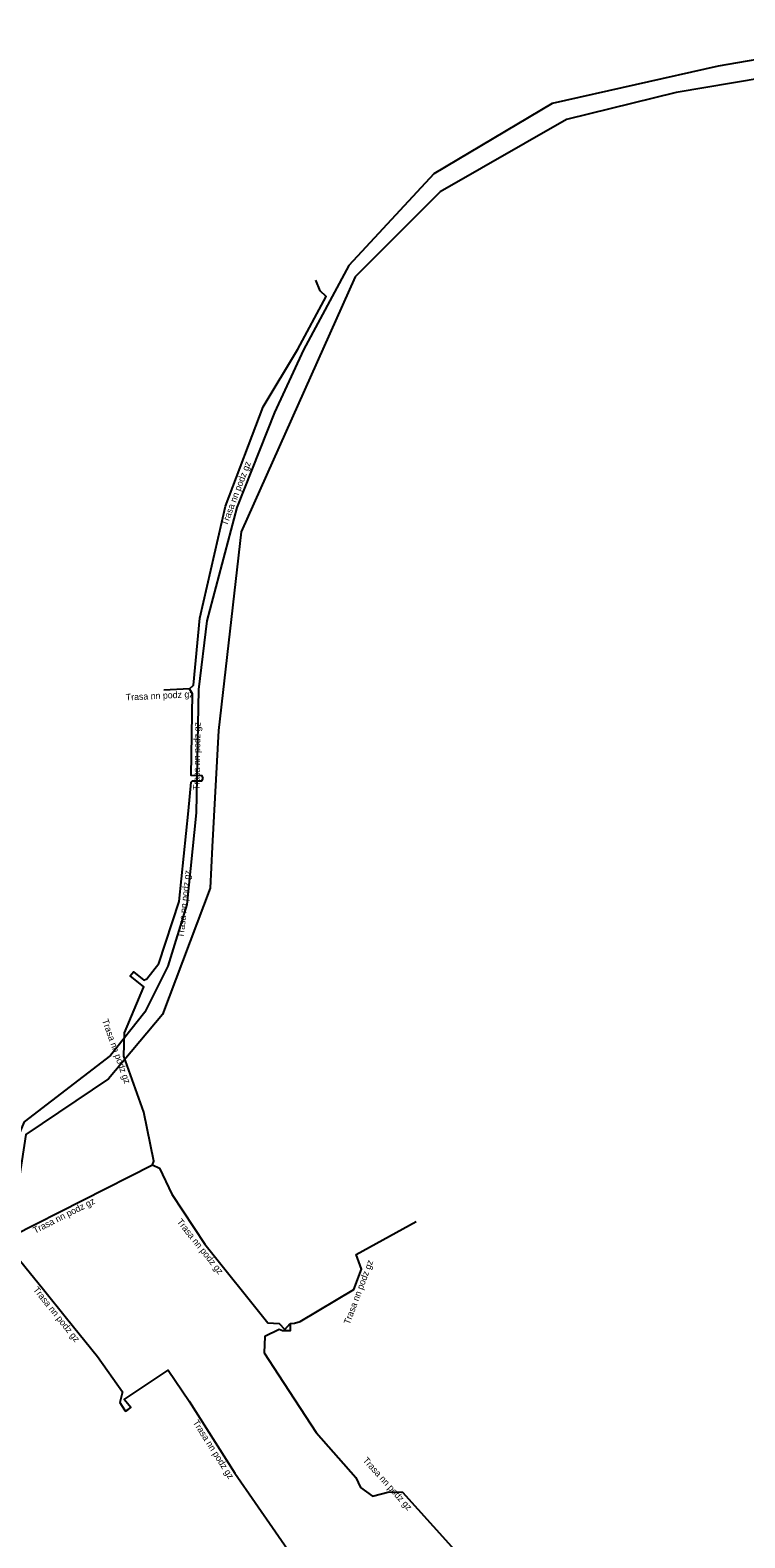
# Model space of a CAD drawing. Extents: x -484846 to -484244, y -1128177 to -1127608.
# Drawn here: x -484548.8 to -484494.4, y -1127972.3 to -1127857.6 of the extents above; entities that cross this region are included whole.
import ezdxf

# ---------------------------------------------------------------- set-up
doc = ezdxf.new("R2010")
doc.units = 0
for name, color, linetype in [('Popiskový text - Ostatní atributy Trasy', 7, 'Continuous'), ('Spojnice NN', 7, 'Continuous'), ('Spojnice VN', 7, 'Continuous')]:
    doc.layers.add(name, color=color, linetype=linetype)

msp = doc.modelspace()

# ---------------------------------------------------------------- linework, layer by layer
at = {"layer": 'Spojnice NN'}
for points in [[(-484536.68, -1127907.69), (-484536.38, -1127907.4), (-484535.89, -1127902.32), (-484533.94, -1127893.79), (-484531.09, -1127886.25), (-484528.45, -1127881.86), (-484526.3, -1127877.86), (-484526.76, -1127877.43), (-484527.07, -1127876.6)], [(-484536.68, -1127907.69), (-484538.64, -1127907.79)], [(-484535.65, -1127914.51), (-484535.73, -1127914.3), (-484536.56, -1127914.28), (-484536.47, -1127908.06), (-484536.61, -1127907.82), (-484536.68, -1127907.69)], [(-484541.07, -1127929.38), (-484540.94, -1127929.22), (-484540.17, -1127929.84), (-484539.92, -1127929.74), (-484539.03, -1127928.57), (-484537.48, -1127923.87), (-484536.76, -1127916.96), (-484536.56, -1127914.8), (-484536.47, -1127914.69), (-484535.74, -1127914.7), (-484535.65, -1127914.51)], [(-484539.5, -1127943.9), (-484539.39, -1127943.62), (-484540.17, -1127939.88), (-484541.69, -1127935.63), (-484541.63, -1127933.85), (-484540.15, -1127930.36), (-484541.19, -1127929.53), (-484541.07, -1127929.38)], [(-484550.99, -1127949.7), (-484550.64, -1127949.47), (-484550.11, -1127949.26), (-484539.5, -1127943.9)], [(-484539.5, -1127943.9), (-484538.97, -1127944.16), (-484538.02, -1127946.13), (-484535.51, -1127949.92), (-484530.72, -1127955.92), (-484529.87, -1127955.96), (-484529.44, -1127956.42), (-484529.04, -1127955.97)], [(-484529.04, -1127955.97), (-484528.71, -1127955.95), (-484528.26, -1127955.81), (-484524.19, -1127953.38), (-484523.61, -1127951.83), (-484524, -1127950.71), (-484519.44, -1127948.2)], [(-484550.99, -1127949.7), (-484550.63, -1127949.87), (-484547.79, -1127953.38), (-484546.05, -1127955.55), (-484543.69, -1127958.48), (-484541.77, -1127961.17), (-484541.98, -1127961.96), (-484541.62, -1127962.54), (-484541.55, -1127962.64), (-484541.35, -1127962.5)], [(-484529.04, -1127955.97), (-484529.03, -1127956.51), (-484529.62, -1127956.51), (-484529.86, -1127956.41), (-484530.96, -1127956.96), (-484531.02, -1127958.2), (-484529.91, -1127959.88), (-484527.05, -1127964.26), (-484524.04, -1127967.67), (-484523.69, -1127968.43), (-484522.78, -1127969.09), (-484521.5, -1127968.78), (-484520.49, -1127968.8), (-484514.43, -1127975.5), (-484511.22, -1127979.06), (-484508.05, -1127982.62), (-484507.53, -1127982.75), (-484506.74, -1127982.23)], [(-484541.35, -1127962.5), (-484541.16, -1127962.36), (-484541.65, -1127961.74), (-484538.3, -1127959.51), (-484536.72, -1127961.87), (-484533.23, -1127967.36), (-484528.6, -1127974.03), (-484531.16, -1127976.24), (-484530.58, -1127976.61)]]:
    msp.add_lwpolyline(points, dxfattribs=at)
at = {"layer": 'Spojnice VN'}
for points in [[(-484480.59, -1127857.59), (-484496.47, -1127860.34), (-484509.11, -1127863.16), (-484518.1, -1127868.51), (-484524.57, -1127875.5), (-484528.02, -1127881.9), (-484530.22, -1127886.66), (-484533.08, -1127893.91), (-484535.38, -1127902.51), (-484535.99, -1127907.75), (-484536.19, -1127917.12), (-484536.89, -1127924.1), (-484538.34, -1127928.78), (-484540.08, -1127932.28), (-484542.7, -1127935.58), (-484549.25, -1127940.63), (-484549.9, -1127942.12), (-484551.08, -1127945.75), (-484553.96, -1127949.92), (-484554.82, -1127954.96), (-484559.11, -1127958.53), (-484565.17, -1127960.65), (-484570.35, -1127962.86), (-484583.75, -1127966)], [(-484480.59, -1127857.59), (-484496.47, -1127860.34), (-484509.11, -1127863.16), (-484518.1, -1127868.51), (-484524.57, -1127875.5), (-484528.02, -1127881.9), (-484530.22, -1127886.66), (-484533.08, -1127893.91), (-484535.38, -1127902.51), (-484535.99, -1127907.75), (-484536.19, -1127917.12), (-484536.89, -1127924.1), (-484538.34, -1127928.78), (-484540.08, -1127932.28), (-484542.7, -1127935.58), (-484549.25, -1127940.63), (-484549.9, -1127942.12), (-484551.08, -1127945.75), (-484553.96, -1127949.92), (-484554.82, -1127954.96), (-484559.11, -1127958.53), (-484565.17, -1127960.65), (-484570.35, -1127962.86), (-484583.75, -1127966)], [(-484480.12, -1127859.03), (-484499.66, -1127862.34), (-484508.01, -1127864.39), (-484517.63, -1127869.9), (-484524.09, -1127876.36), (-484532.76, -1127895.75), (-484534.49, -1127910.87), (-484534.96, -1127919.7), (-484535.12, -1127922.85), (-484538.74, -1127932.46), (-484542.84, -1127937.35), (-484549.14, -1127941.6), (-484549.62, -1127944.75), (-484553.08, -1127949.8), (-484553.56, -1127955.47), (-484557.65, -1127959.09), (-484581.34, -1127966.42), (-484583.75, -1127966)]]:
    msp.add_lwpolyline(points, dxfattribs=at)

# ---------------------------------------------------------------- texts
at = {"layer": 'Popiskový text - Ostatní atributy Trasy'}
for rotation, p in [(69.2942, (-484533.83, -1127895.33)), (2.8055, (-484541.52, -1127908.58)), (89.1808, (-484535.92, -1127915.39)), (84.0514, (-484537.12, -1127926.65)), (289.6794, (-484543.35, -1127932.91)), (26.7844, (-484548.43, -1127949.14)), (308.6015, (-484537.68, -1127948.24)), (69.4845, (-484524.51, -1127956.08)), (308.8501, (-484548.61, -1127953.41)), (302.4442, (-484536.46, -1127963.49)), (312.1435, (-484523.54, -1127966.4))]:
    msp.add_text('Trasa nn podz gz', height=0.5, rotation=rotation, dxfattribs=at).set_placement(p)

doc.saveas('drawing.dxf')
